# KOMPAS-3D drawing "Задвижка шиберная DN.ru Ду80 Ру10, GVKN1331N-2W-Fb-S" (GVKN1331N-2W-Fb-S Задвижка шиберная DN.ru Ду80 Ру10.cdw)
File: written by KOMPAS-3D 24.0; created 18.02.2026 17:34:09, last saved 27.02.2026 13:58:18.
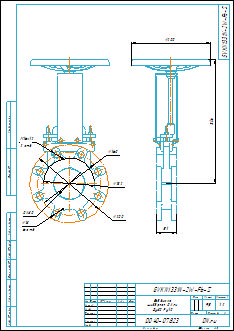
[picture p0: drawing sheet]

Document properties: art: D040-07823; Автор: R2D2; Форматы листов документа: A3; Полное имя файла: GVKN1331N-2W-Fb-S Задвижка шиберная DN.ru Ду80 Ру10.m3d; Масса: 9.5; Наименование: Задвижка шиберная DN.ru Ду80 Ру10; Количество листов документа: 1; Примечание: D040-07823

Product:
- Part/product: Задвижка шиберная DN.ru Ду80 Ру10  | designation GVKN1331N-2W-Fb-S
    Масса: 9.5
    Раздел спецификации: Прочие изделия
    Форматы листов документа: A3
    Примечание: D040-07823
    additional columns: D040-07823

Views: Вид 1, Спереди
Referenced files in E:\Работа\Зайцев\GVKN1331N-2W-Fb-S Задвижка шиберная DN.ru Ду50-300 Ру10\DN80\: GVKN1331N-2W-Fb-S Задвижка шиберная DN.ru Ду80 Ру10.m3d
Referenced files in E:\Работа\Зайцев\Для компаса\: чертеж DN.ru.cdt
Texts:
  Диаметральный размер
  GVKN1331N-2W-Fb-S
  чертеж DN.ru.cdt
  Задвижка
  шиберная DN.ru
  Ду80 Ру10
  prop
  Задвижка шиберная DN.ru Ду80 Ру10
  GVKN1331N-2W-Fb-S Задвижка шиберная DN.ru Ду80 Ру10
Dimensions and other numbers on the sheet: 0; 3; 2; 4; 16; 2 отв.; 18; 6 отв.; 200; 160; 132; 80; 1:2; 1; 9,5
